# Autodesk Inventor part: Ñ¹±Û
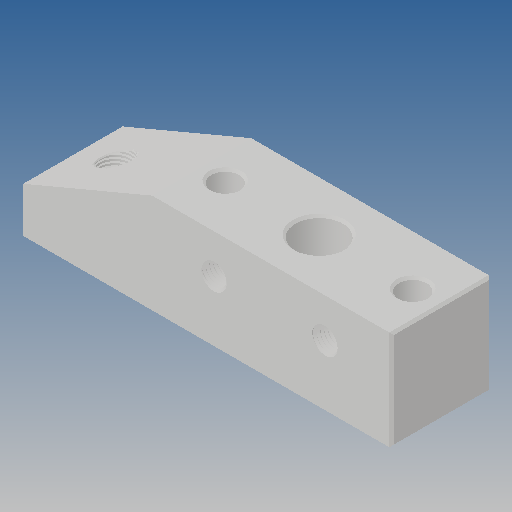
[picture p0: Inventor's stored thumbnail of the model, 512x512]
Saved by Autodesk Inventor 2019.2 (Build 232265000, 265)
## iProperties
Created: 2013-09
Part Number: Ñ¹±Û
Material: Ogólny
Document SubType Name: Modeling
Designer: CADENGINEERING4
Density: 1 g/cm^3
Appearance: Domyślna
Author: CADENGINEERING4
Revision Number: ÈÎºÎ
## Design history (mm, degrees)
feature "µ¹½Ç9"
node "Bryła1"
